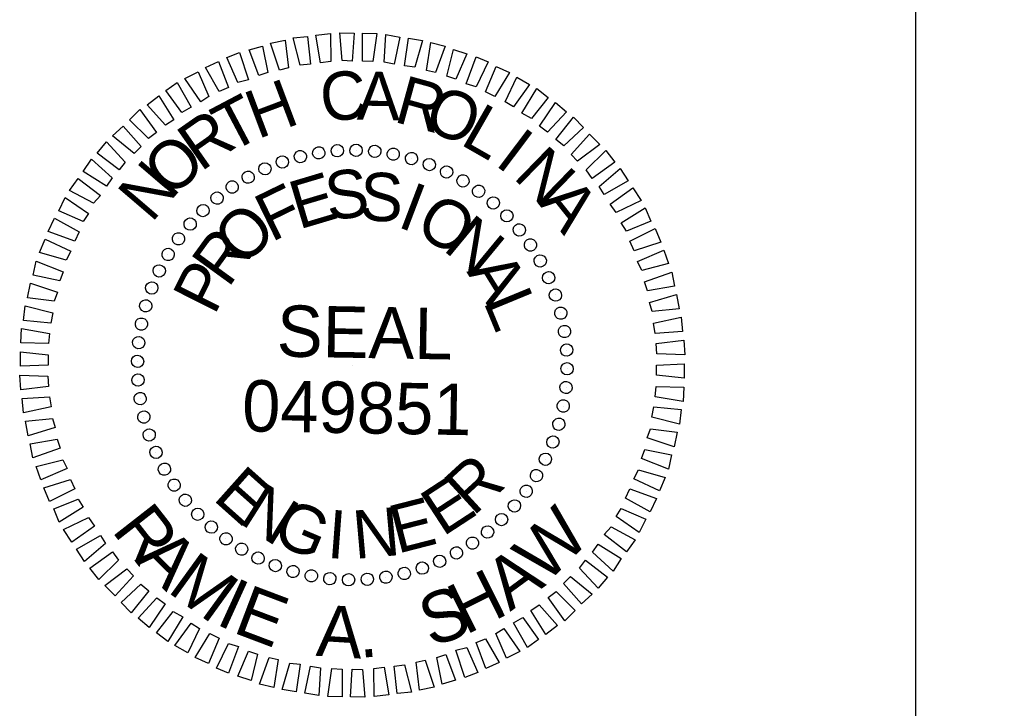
# Model space of a CAD drawing. Extents: x 2294342 to 2294901, y 719427 to 719941.
# Drawn here: x 2294739.82 to 2294764.08, y 719905.92 to 719922.69 of the extents above; entities that cross this region are included whole.
import ezdxf

# ---------------------------------------------------------------- set-up
doc = ezdxf.new("R2010")
doc.units = 0
for name, color, linetype in [('Default', 7, 'Continuous'), ('Old_Level_2', 7, 'Continuous'), ('Sheet Plan CELL', 7, 'Continuous')]:
    doc.layers.add(name, color=color, linetype=linetype)

msp = doc.modelspace()

# ---------------------------------------------------------------- linework, layer by layer
at = {"layer": 'Old_Level_2'}
for p, q in [((2294747.103, 719919.441), (2294747.103, 719919.441)), ((2294747.551, 719919.504), (2294747.551, 719919.504)), ((2294748.01, 719919.514), (2294748.01, 719919.514)), ((2294748.469, 719919.483), (2294748.469, 719919.483)), ((2294746.206, 719919.233), (2294746.206, 719919.233)), ((2294746.644, 719919.358), (2294746.644, 719919.358)), ((2294748.917, 719919.41), (2294748.917, 719919.41)), ((2294749.355, 719919.316), (2294749.355, 719919.316)), ((2294749.794, 719919.17), (2294749.794, 719919.17)), ((2294745.789, 719919.066), (2294745.789, 719919.066)), ((2294750.211, 719918.983), (2294750.211, 719918.983)), ((2294745.382, 719918.857), (2294745.382, 719918.857)), ((2294750.617, 719918.774), (2294750.617, 719918.774)), ((2294744.986, 719918.618), (2294744.986, 719918.618)), ((2294750.993, 719918.513), (2294750.993, 719918.513)), ((2294744.62, 719918.357), (2294744.62, 719918.357)), ((2294751.358, 719918.232), (2294751.358, 719918.232)), ((2294744.276, 719918.044), (2294744.276, 719918.044)), ((2294743.963, 719917.721), (2294743.963, 719917.721)), ((2294751.681, 719917.919), (2294751.681, 719917.919)), ((2294751.994, 719917.575), (2294751.994, 719917.575)), ((2294743.682, 719917.356), (2294743.682, 719917.356)), ((2294752.255, 719917.21), (2294752.255, 719917.21)), ((2294743.421, 719916.98), (2294743.421, 719916.98)), ((2294752.495, 719916.813), (2294752.495, 719916.813)), ((2294743.213, 719916.573), (2294743.213, 719916.573)), ((2294752.703, 719916.407), (2294752.703, 719916.407)), ((2294743.025, 719916.156), (2294743.025, 719916.156)), ((2294752.87, 719915.989), (2294752.87, 719915.989)), ((2294742.879, 719915.718), (2294742.879, 719915.718)), ((2294752.995, 719915.551), (2294752.995, 719915.551)), ((2294742.785, 719915.28), (2294742.785, 719915.28)), ((2294753.079, 719915.092), (2294753.079, 719915.092)), ((2294742.712, 719914.832), (2294742.712, 719914.832)), ((2294753.141, 719914.644), (2294753.141, 719914.644)), ((2294742.681, 719914.373), (2294742.681, 719914.373)), ((2294747.916, 719914.279), (2294747.916, 719914.279)), ((2294753.152, 719914.185), (2294753.152, 719914.185)), ((2294742.691, 719913.914), (2294742.691, 719913.914)), ((2294753.121, 719913.726), (2294753.121, 719913.726)), ((2294742.754, 719913.465), (2294742.754, 719913.465)), ((2294753.047, 719913.278), (2294753.047, 719913.278)), ((2294742.837, 719913.006), (2294742.837, 719913.006)), ((2294752.954, 719912.84), (2294752.954, 719912.84)), ((2294742.962, 719912.568), (2294742.962, 719912.568)), ((2294752.808, 719912.402), (2294752.808, 719912.402)), ((2294743.129, 719912.151), (2294743.129, 719912.151)), ((2294752.62, 719911.984), (2294752.62, 719911.984)), ((2294743.338, 719911.745), (2294743.338, 719911.745)), ((2294752.411, 719911.578), (2294752.411, 719911.578)), ((2294743.578, 719911.348), (2294743.578, 719911.348)), ((2294752.151, 719911.202), (2294752.151, 719911.202)), ((2294743.838, 719910.983), (2294743.838, 719910.983)), ((2294751.869, 719910.837), (2294751.869, 719910.837)), ((2294744.151, 719910.639), (2294744.151, 719910.639)), ((2294751.556, 719910.514), (2294751.556, 719910.514)), ((2294744.474, 719910.326), (2294744.474, 719910.326)), ((2294751.212, 719910.201), (2294751.212, 719910.201)), ((2294744.84, 719910.045), (2294744.84, 719910.045)), ((2294745.215, 719909.784), (2294745.215, 719909.784)), ((2294750.847, 719909.94), (2294750.847, 719909.94)), ((2294745.622, 719909.575), (2294745.622, 719909.575)), ((2294750.044, 719909.492), (2294750.044, 719909.492)), ((2294750.451, 719909.7), (2294750.451, 719909.7)), ((2294746.039, 719909.387), (2294746.039, 719909.387)), ((2294746.477, 719909.241), (2294746.477, 719909.241)), ((2294749.627, 719909.325), (2294749.627, 719909.325)), ((2294746.915, 719909.148), (2294746.915, 719909.148)), ((2294747.363, 719909.075), (2294747.363, 719909.075)), ((2294747.822, 719909.043), (2294747.822, 719909.043)), ((2294748.281, 719909.054), (2294748.281, 719909.054)), ((2294748.73, 719909.116), (2294748.73, 719909.116)), ((2294749.189, 719909.2), (2294749.189, 719909.2))]:
    msp.add_line(p, q, dxfattribs=at)
for points in [[(2294747.144, 719921.642), (2294747.03, 719922.31), (2294747.384, 719922.351), (2294747.395, 719921.673)], [(2294747.666, 719921.694), (2294747.614, 719922.372), (2294747.958, 719922.362), (2294747.916, 719921.684)], [(2294748.167, 719921.684), (2294748.167, 719922.362), (2294748.511, 719922.351), (2294748.417, 719921.673)], [(2294748.688, 719921.653), (2294748.73, 719922.33), (2294749.074, 719922.268), (2294748.938, 719921.611)], [(2294746.143, 719921.465), (2294745.924, 719922.122), (2294746.279, 719922.195), (2294746.362, 719921.517)], [(2294746.644, 719921.58), (2294746.477, 719922.247), (2294746.821, 719922.278), (2294746.894, 719921.611)], [(2294749.189, 719921.569), (2294749.282, 719922.237), (2294749.627, 719922.184), (2294749.439, 719921.538)], [(2294749.72, 719921.454), (2294749.825, 719922.132), (2294750.179, 719922.049), (2294749.94, 719921.402)], [(2294745.132, 719921.162), (2294744.86, 719921.767), (2294745.173, 719921.892), (2294745.392, 719921.225)], [(2294745.643, 719921.329), (2294745.403, 719921.955), (2294745.726, 719922.049), (2294745.862, 719921.402)], [(2294750.221, 719921.319), (2294750.378, 719921.965), (2294750.701, 719921.861), (2294750.44, 719921.246)], [(2294744.673, 719920.943), (2294744.339, 719921.527), (2294744.662, 719921.673), (2294744.902, 719921.037)], [(2294750.69, 719921.131), (2294750.93, 719921.788), (2294751.222, 719921.663), (2294750.93, 719921.058)], [(2294744.224, 719920.693), (2294743.838, 719921.256), (2294744.162, 719921.423), (2294744.422, 719920.818)], [(2294751.16, 719920.933), (2294751.42, 719921.548), (2294751.744, 719921.402), (2294751.389, 719920.818)], [(2294743.765, 719920.432), (2294743.379, 719920.964), (2294743.651, 719921.162), (2294743.995, 719920.557)], [(2294751.64, 719920.693), (2294751.921, 719921.287), (2294752.234, 719921.11), (2294751.838, 719920.568)], [(2294752.046, 719920.411), (2294752.411, 719921.016), (2294752.682, 719920.797), (2294752.276, 719920.286)], [(2294743.369, 719920.119), (2294742.92, 719920.62), (2294743.202, 719920.839), (2294743.567, 719920.255)], [(2294752.474, 719920.099), (2294752.86, 719920.672), (2294753.131, 719920.443), (2294752.672, 719919.953)], [(2294742.952, 719919.796), (2294742.493, 719920.255), (2294742.743, 719920.505), (2294743.15, 719919.942)], [(2294752.87, 719919.775), (2294753.298, 719920.318), (2294753.548, 719920.067), (2294753.068, 719919.619)], [(2294742.608, 719919.431), (2294742.076, 719919.859), (2294742.336, 719920.099), (2294742.774, 719919.598)], [(2294753.246, 719919.41), (2294753.694, 719919.9), (2294753.944, 719919.65), (2294753.402, 719919.243)], [(2294742.243, 719919.035), (2294741.7, 719919.441), (2294741.93, 719919.713), (2294742.389, 719919.222)], [(2294753.611, 719919.035), (2294754.09, 719919.504), (2294754.309, 719919.222), (2294753.757, 719918.826)], [(2294741.93, 719918.638), (2294741.366, 719918.993), (2294741.565, 719919.295), (2294742.065, 719918.837)], [(2294753.924, 719918.628), (2294754.435, 719919.066), (2294754.633, 719918.764), (2294754.049, 719918.43)], [(2294741.617, 719918.221), (2294741.033, 719918.534), (2294741.241, 719918.826), (2294741.784, 719918.409)], [(2294754.195, 719918.2), (2294754.747, 719918.597), (2294754.946, 719918.284), (2294754.341, 719917.992)], [(2294741.366, 719917.773), (2294740.772, 719918.033), (2294740.928, 719918.357), (2294741.492, 719917.971)], [(2294754.466, 719917.741), (2294755.05, 719918.107), (2294755.186, 719917.783), (2294754.591, 719917.543)], [(2294741.158, 719917.293), (2294740.511, 719917.533), (2294740.668, 719917.856), (2294741.262, 719917.522)], [(2294754.674, 719917.293), (2294755.29, 719917.606), (2294755.425, 719917.272), (2294754.779, 719917.064)], [(2294740.949, 719916.834), (2294740.303, 719917.022), (2294740.438, 719917.345), (2294741.064, 719917.053)], [(2294754.862, 719916.803), (2294755.498, 719917.074), (2294755.613, 719916.751), (2294754.967, 719916.584)], [(2294740.793, 719916.333), (2294740.146, 719916.469), (2294740.219, 719916.813), (2294740.876, 719916.553)], [(2294755.029, 719916.302), (2294755.697, 719916.542), (2294755.759, 719916.198), (2294755.102, 719916.083)], [(2294740.657, 719915.833), (2294740.011, 719915.916), (2294740.084, 719916.271), (2294740.741, 719916.052)], [(2294755.154, 719915.802), (2294755.811, 719916), (2294755.874, 719915.645), (2294755.217, 719915.583)], [(2294740.574, 719915.301), (2294739.906, 719915.364), (2294739.948, 719915.718), (2294740.626, 719915.551)], [(2294755.248, 719915.301), (2294755.926, 719915.447), (2294755.957, 719915.092), (2294755.29, 719915.051)], [(2294740.522, 719914.8), (2294739.844, 719914.821), (2294739.865, 719915.165), (2294740.543, 719915.051)], [(2294755.311, 719914.8), (2294755.989, 719914.884), (2294756.009, 719914.529), (2294755.332, 719914.55)], [(2294740.511, 719914.279), (2294739.833, 719914.248), (2294739.833, 719914.602), (2294740.511, 719914.529)], [(2294755.321, 719914.279), (2294755.999, 719914.31), (2294755.999, 719913.956), (2294755.321, 719914.029)], [(2294740.522, 719913.757), (2294739.844, 719913.674), (2294739.823, 719914.029), (2294740.501, 719914.008)], [(2294755.311, 719913.757), (2294755.989, 719913.737), (2294755.968, 719913.392), (2294755.29, 719913.507)], [(2294740.584, 719913.257), (2294739.906, 719913.111), (2294739.875, 719913.465), (2294740.543, 719913.507)], [(2294755.259, 719913.257), (2294755.926, 719913.194), (2294755.884, 719912.84), (2294755.206, 719913.006)], [(2294740.678, 719912.756), (2294740.021, 719912.558), (2294739.959, 719912.913), (2294740.616, 719912.975)], [(2294755.175, 719912.725), (2294755.822, 719912.641), (2294755.749, 719912.287), (2294755.092, 719912.506)], [(2294740.803, 719912.256), (2294740.136, 719912.016), (2294740.073, 719912.36), (2294740.73, 719912.475)], [(2294755.04, 719912.224), (2294755.686, 719912.089), (2294755.613, 719911.745), (2294754.956, 719912.005)], [(2294740.97, 719911.755), (2294740.334, 719911.484), (2294740.219, 719911.807), (2294740.866, 719911.974)], [(2294754.883, 719911.724), (2294755.53, 719911.536), (2294755.394, 719911.213), (2294754.768, 719911.505)], [(2294741.158, 719911.265), (2294740.543, 719910.952), (2294740.407, 719911.286), (2294741.054, 719911.494)], [(2294754.674, 719911.265), (2294755.321, 719911.025), (2294755.165, 719910.702), (2294754.57, 719911.035)], [(2294741.366, 719910.816), (2294740.782, 719910.451), (2294740.647, 719910.775), (2294741.241, 719911.014)], [(2294754.466, 719910.785), (2294755.06, 719910.524), (2294754.904, 719910.201), (2294754.341, 719910.587)], [(2294741.638, 719910.357), (2294741.085, 719909.961), (2294740.887, 719910.274), (2294741.492, 719910.566)], [(2294754.216, 719910.337), (2294754.8, 719910.024), (2294754.591, 719909.732), (2294754.049, 719910.149)], [(2294741.909, 719909.93), (2294741.398, 719909.492), (2294741.2, 719909.794), (2294741.784, 719910.128)], [(2294742.222, 719909.523), (2294741.742, 719909.054), (2294741.523, 719909.335), (2294742.076, 719909.732)], [(2294753.903, 719909.919), (2294754.466, 719909.565), (2294754.268, 719909.262), (2294753.767, 719909.721)], [(2294753.59, 719909.523), (2294754.132, 719909.116), (2294753.903, 719908.845), (2294753.444, 719909.335)], [(2294742.587, 719909.148), (2294742.138, 719908.657), (2294741.888, 719908.908), (2294742.43, 719909.314)], [(2294753.225, 719909.127), (2294753.757, 719908.699), (2294753.496, 719908.459), (2294753.058, 719908.96)], [(2294742.962, 719908.783), (2294742.535, 719908.24), (2294742.284, 719908.491), (2294742.764, 719908.939)], [(2294752.881, 719908.762), (2294753.34, 719908.303), (2294753.089, 719908.052), (2294752.682, 719908.616)], [(2294743.359, 719908.459), (2294742.973, 719907.886), (2294742.701, 719908.115), (2294743.16, 719908.605)], [(2294743.786, 719908.146), (2294743.421, 719907.541), (2294743.15, 719907.76), (2294743.557, 719908.272)], [(2294752.463, 719908.438), (2294752.912, 719907.938), (2294752.63, 719907.719), (2294752.265, 719908.303)], [(2294752.067, 719908.126), (2294752.453, 719907.594), (2294752.182, 719907.395), (2294751.838, 719908)], [(2294744.193, 719907.865), (2294743.911, 719907.27), (2294743.598, 719907.448), (2294743.995, 719907.99)], [(2294751.608, 719907.865), (2294751.994, 719907.302), (2294751.671, 719907.135), (2294751.41, 719907.74)], [(2294744.673, 719907.625), (2294744.412, 719907.01), (2294744.089, 719907.156), (2294744.443, 719907.74)], [(2294751.16, 719907.614), (2294751.494, 719907.03), (2294751.17, 719906.884), (2294750.93, 719907.521)], [(2294745.142, 719907.427), (2294744.902, 719906.77), (2294744.61, 719906.895), (2294744.902, 719907.5)], [(2294745.611, 719907.239), (2294745.455, 719906.592), (2294745.132, 719906.697), (2294745.392, 719907.312)], [(2294750.701, 719907.395), (2294750.972, 719906.791), (2294750.659, 719906.665), (2294750.44, 719907.333)], [(2294746.112, 719907.103), (2294746.008, 719906.425), (2294745.653, 719906.509), (2294745.893, 719907.156)], [(2294749.689, 719907.093), (2294749.908, 719906.436), (2294749.554, 719906.363), (2294749.47, 719907.041)], [(2294750.19, 719907.229), (2294750.43, 719906.603), (2294750.106, 719906.509), (2294749.971, 719907.156)], [(2294746.644, 719906.989), (2294746.55, 719906.321), (2294746.206, 719906.373), (2294746.393, 719907.02)], [(2294747.144, 719906.905), (2294747.103, 719906.227), (2294746.759, 719906.29), (2294746.894, 719906.947)], [(2294747.666, 719906.874), (2294747.666, 719906.196), (2294747.322, 719906.206), (2294747.416, 719906.884)], [(2294748.167, 719906.864), (2294748.219, 719906.186), (2294747.874, 719906.196), (2294747.916, 719906.874)], [(2294748.688, 719906.916), (2294748.803, 719906.248), (2294748.448, 719906.206), (2294748.438, 719906.884)], [(2294749.189, 719906.978), (2294749.355, 719906.311), (2294749.011, 719906.279), (2294748.938, 719906.947)]]:
    msp.add_lwpolyline(points, close=True, dxfattribs=at)
for centre, major_axis in [((2294748.007, 719919.51), (0.003, 0.15)), ((2294746.651, 719919.355), (-0.036, 0.146)), ((2294747.098, 719919.446), (-0.023, 0.148)), ((2294747.551, 719919.498), (-0.01, 0.15)), ((2294748.463, 719919.482), (0.016, 0.149)), ((2294748.914, 719919.414), (0.029, 0.147)), ((2294749.358, 719919.308), (0.041, 0.144)), ((2294745.788, 719919.058), (-0.061, 0.137)), ((2294746.213, 719919.225), (-0.049, 0.142)), ((2294749.791, 719919.163), (0.054, 0.14)), ((2294745.38, 719918.854), (-0.073, 0.131)), ((2294750.21, 719918.981), (0.066, 0.135)), ((2294750.611, 719918.763), (0.077, 0.129)), ((2294744.991, 719918.616), (-0.084, 0.125)), ((2294744.624, 719918.344), (-0.095, 0.117)), ((2294750.991, 719918.511), (0.088, 0.122)), ((2294744.282, 719918.042), (-0.104, 0.108)), ((2294751.348, 719918.227), (0.099, 0.113)), ((2294751.679, 719917.913), (0.108, 0.104)), ((2294743.968, 719917.711), (-0.113, 0.099)), ((2294751.982, 719917.571), (0.117, 0.095)), ((2294743.684, 719917.354), (-0.122, 0.088)), ((2294752.253, 719917.204), (0.125, 0.084)), ((2294743.432, 719916.973), (-0.129, 0.077)), ((2294752.492, 719916.815), (0.131, 0.073)), ((2294743.214, 719916.572), (-0.135, 0.066)), ((2294752.695, 719916.407), (0.137, 0.061)), ((2294743.032, 719916.154), (-0.14, 0.054)), ((2294752.863, 719915.982), (0.142, 0.049)), ((2294742.887, 719915.721), (-0.144, 0.041)), ((2294752.992, 719915.544), (0.146, 0.036)), ((2294742.781, 719915.277), (-0.147, 0.029)), ((2294753.083, 719915.097), (0.148, 0.023)), ((2294742.713, 719914.826), (-0.149, 0.016)), ((2294753.135, 719914.644), (0.15, 0.01)), ((2294742.686, 719914.37), (-0.15, 0.003)), ((2294753.147, 719914.188), (0.15, -0.003)), ((2294742.698, 719913.914), (-0.15, -0.01)), ((2294753.119, 719913.732), (0.149, -0.016)), ((2294742.749, 719913.461), (-0.148, -0.023)), ((2294753.052, 719913.281), (0.147, -0.029)), ((2294742.84, 719913.013), (-0.146, -0.036)), ((2294752.945, 719912.837), (0.144, -0.041)), ((2294742.97, 719912.576), (-0.142, -0.049)), ((2294752.8, 719912.404), (0.14, -0.054)), ((2294743.137, 719912.151), (-0.137, -0.061)), ((2294752.618, 719911.986), (0.135, -0.066)), ((2294743.341, 719911.743), (-0.131, -0.073)), ((2294752.4, 719911.585), (0.129, -0.077)), ((2294743.579, 719911.354), (-0.125, -0.084)), ((2294752.149, 719911.204), (0.122, -0.088)), ((2294743.851, 719910.987), (-0.117, -0.095)), ((2294751.864, 719910.847), (0.113, -0.099)), ((2294744.153, 719910.645), (-0.108, -0.104)), ((2294751.55, 719910.516), (0.104, -0.108)), ((2294744.484, 719910.331), (-0.099, -0.113)), ((2294744.841, 719910.047), (-0.088, -0.122)), ((2294751.208, 719910.213), (0.095, -0.117)), ((2294745.222, 719909.795), (-0.077, -0.129)), ((2294750.842, 719909.942), (0.084, -0.125)), ((2294745.623, 719909.577), (-0.066, -0.135)), ((2294750.452, 719909.703), (0.073, -0.131)), ((2294746.041, 719909.395), (-0.054, -0.14)), ((2294749.619, 719909.332), (0.049, -0.142)), ((2294750.044, 719909.5), (0.061, -0.137)), ((2294746.474, 719909.25), (-0.041, -0.144)), ((2294746.918, 719909.144), (-0.029, -0.147)), ((2294747.369, 719909.076), (-0.016, -0.149)), ((2294748.735, 719909.112), (0.023, -0.148)), ((2294749.182, 719909.203), (0.036, -0.146)), ((2294747.825, 719909.048), (-0.003, -0.15)), ((2294748.281, 719909.06), (0.01, -0.15))]:
    msp.add_ellipse(centre, major_axis=major_axis, ratio=0.999708, dxfattribs=at)
at = {"layer": 'Sheet Plan CELL'}
msp.add_lwpolyline([(2294787.924, 719903.659), (2294761.64, 719903.659), (2294761.64, 719926.159), (2294787.924, 719926.159)], dxfattribs=at)

# ---------------------------------------------------------------- texts
at = {"layer": 'Default'}
for s, rotation, p in [('R', 308.005, (2294742.036, 719910.247)), ('W', 45.0672, (2294752.625, 719908.918)), ('A', 315.3996, (2294742.602, 719909.523)), ('M', 324.1387, (2294743.383, 719908.771)), ('A', 36.3281, (2294751.758, 719908.265)), ('H', 26.4584, (2294750.673, 719907.695)), ('I', 335.5363, (2294744.558, 719907.983)), ('E', 339.2947, (2294744.976, 719907.776)), ('S', 19.2166, (2294749.824, 719907.4)), ('A', 356.4062, (2294747.015, 719907.198)), ('.', 5.1454, (2294748.098, 719907.143))]:
    msp.add_text(s, height=1.251, rotation=rotation, dxfattribs=at).set_placement(p)
at = {"layer": 'Old_Level_2'}
for s, height, rotation, p in [('C', 1.176, 6.2199, (2294747.197, 719920.192)), ('A', 1.176, 359.0203, (2294748.02, 719920.255)), ('H', 1.176, 20.6195, (2294745.611, 719919.775)), ('R', 1.176, 344.6211, (2294748.897, 719920.213)), ('T', 1.176, 27.8198, (2294744.933, 719919.431)), ('O', 1.176, 337.4212, (2294749.595, 719920.057)), ('L', 1.176, 330.2209, (2294750.513, 719919.671)), ('R', 1.176, 35.0205, (2294744.224, 719918.972)), ('I', 1.176, 323.0201, (2294751.358, 719919.17)), ('O', 1.176, 42.2217, (2294743.505, 719918.326)), ('N', 1.176, 315.8189, (2294751.806, 719918.847)), ('N', 1.176, 49.4235, (2294743.025, 719917.721)), ('E', 1.176, 16.6111, (2294746.613, 719917.575)), ('S', 1.176, 7.2556, (2294747.332, 719917.794)), ('S', 1.176, 357.9004, (2294748.083, 719917.804)), ('F', 1.176, 25.967, (2294745.945, 719917.262)), ('I', 1.176, 339.1896, (2294748.98, 719917.658)), ('A', 1.176, 308.6172, (2294752.422, 719918.232)), ('O', 1.176, 329.8335, (2294749.397, 719917.512)), ('O', 1.176, 44.6812, (2294745.257, 719916.646)), ('N', 1.176, 320.4766, (2294750.096, 719917.095)), ('R', 1.176, 54.0397, (2294744.892, 719916.135)), ('P', 1.176, 63.3989, (2294744.558, 719915.468)), ('A', 1.176, 301.7603, (2294750.69, 719916.553)), ('L', 1.176, 292.4009, (2294751.097, 719915.833)), ('SEAL', 1.2512, 359, (2294746.07, 719914.487)), ('049851', 1.2515, 359, (2294745.225, 719912.666)), ('R', 1.176, 42.4814, (2294750.857, 719910.576)), ('E', 1.176, 318.2769, (2294744.495, 719911.014)), ('E', 1.176, 33.1241, (2294750.117, 719910.086)), ('N', 1.176, 327.634, (2294745.121, 719910.451)), ('G', 1.176, 336.9902, (2294745.914, 719909.982)), ('E', 1.176, 14.4118, (2294749.011, 719909.679)), ('I', 1.176, 355.7012, (2294747.28, 719909.586)), ('N', 1.176, 5.0564, (2294747.979, 719909.554))]:
    msp.add_text(s, height=height, rotation=rotation, dxfattribs=at).set_placement(p)

doc.saveas('drawing.dxf')
